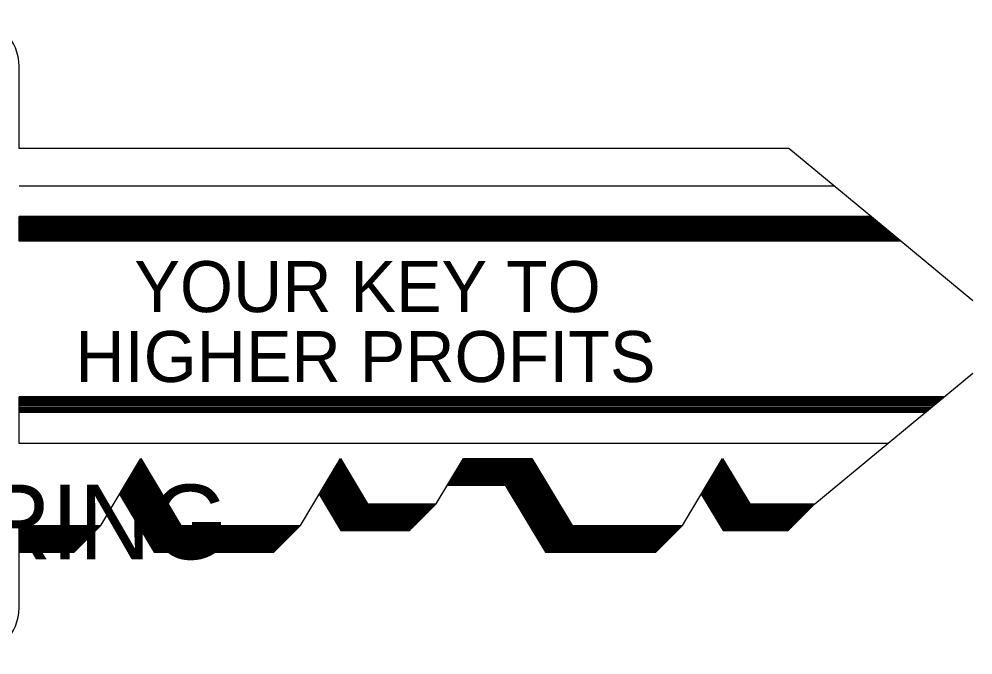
# Model space of a CAD drawing. Extents: x 0 to 13.3, y 0 to 9.3.
# Drawn here: x 1.0443 to 1.466, y 0.4068 to 0.688 of the extents above; entities that cross this region are included whole.
import ezdxf

# ---------------------------------------------------------------- set-up
doc = ezdxf.new("R2010")
doc.units = 0
doc.layers.add('Level 1', color=7, linetype='Continuous')

msp = doc.modelspace()

# ---------------------------------------------------------------- linework, layer by layer
at = {"layer": 'Level 1'}
for p, q in [((1.04429, 0.63074), (1.04429, 0.6672)), ((1.38463, 0.63074), (1.04429, 0.63074)), ((1.434, 0.58991), (1.38471, 0.63074)), ((1.40479, 0.61407), (1.04429, 0.61407)), ((1.04429, 0.58978), (1.04429, 0.60066)), ((1.421, 0.60066), (1.04429, 0.60066)), ((1.42133, 0.60041), (1.04429, 0.60041)), ((1.42163, 0.60016), (1.04429, 0.60016)), ((1.42196, 0.59986), (1.04429, 0.59986)), ((1.42233, 0.59957), (1.04429, 0.59957)), ((1.42267, 0.59928), (1.04429, 0.59928)), ((1.42308, 0.59895), (1.04429, 0.59895)), ((1.42342, 0.59866), (1.04429, 0.59866)), ((1.42383, 0.59832), (1.04429, 0.59832)), ((1.42425, 0.59799), (1.04429, 0.59799)), ((1.42458, 0.5977), (1.04429, 0.5977)), ((1.42496, 0.59736), (1.04429, 0.59736)), ((1.42542, 0.59703), (1.04429, 0.59703)), ((1.42575, 0.59674), (1.04429, 0.59674)), ((1.42608, 0.59645), (1.04429, 0.59645)), ((1.4265, 0.59611), (1.04429, 0.59611)), ((1.42692, 0.59578), (1.04429, 0.59578)), ((1.42729, 0.59545), (1.04429, 0.59545)), ((1.42775, 0.59507), (1.04429, 0.59507)), ((1.42813, 0.59478), (1.04429, 0.59478)), ((1.42488, 0.59745), (1.42475, 0.59757)), ((1.42508, 0.59728), (1.42488, 0.59745)), ((1.42638, 0.5962), (1.42508, 0.59728)), ((1.42696, 0.59574), (1.42638, 0.5962)), ((1.4285, 0.59445), (1.04429, 0.59445)), ((1.42896, 0.59407), (1.04429, 0.59407)), ((1.42938, 0.59374), (1.04429, 0.59374)), ((1.42967, 0.59349), (1.04429, 0.59349)), ((1.43008, 0.59316), (1.04429, 0.59316)), ((1.43046, 0.59282), (1.04429, 0.59282)), ((1.43083, 0.59253), (1.04429, 0.59253)), ((1.43117, 0.59224), (1.04429, 0.59224)), ((1.4315, 0.59199), (1.04429, 0.59199)), ((1.43196, 0.59161), (1.04429, 0.59161)), ((1.43225, 0.59136), (1.04429, 0.59136)), ((1.43258, 0.59107), (1.04429, 0.59107)), ((1.43288, 0.59082), (1.04429, 0.59082)), ((1.43321, 0.59057), (1.04429, 0.59057)), ((1.43346, 0.59036), (1.04429, 0.59036)), ((1.43375, 0.59011), (1.04429, 0.59011)), ((1.43396, 0.58995), (1.04429, 0.58995)), ((1.43417, 0.58978), (1.04429, 0.58978)), ((1.43417, 0.58978), (1.434, 0.58991)), ((1.46604, 0.56345), (1.43417, 0.58978)), ((1.39613, 0.47357), (1.46604, 0.53136)), ((1.45346, 0.52095), (1.04429, 0.52095)), ((1.04429, 0.50028), (1.04429, 0.52095)), ((1.45279, 0.52041), (1.04429, 0.52041)), ((1.45208, 0.51982), (1.04429, 0.51982)), ((1.45129, 0.51916), (1.04429, 0.51916)), ((1.45063, 0.51861), (1.04429, 0.51861)), ((1.44983, 0.51795), (1.04429, 0.51795)), ((1.44913, 0.51736), (1.04429, 0.51736)), ((1.44838, 0.51674), (1.04429, 0.51674)), ((1.44754, 0.51607), (1.04429, 0.51607)), ((1.44679, 0.51545), (1.04429, 0.51545)), ((1.44608, 0.51486), (1.04429, 0.51486)), ((1.44558, 0.51445), (1.04429, 0.51445)), ((1.44513, 0.51407), (1.04429, 0.51407)), ((1.42846, 0.50028), (1.04429, 0.50028)), ((1.08042, 0.46407), (1.09813, 0.49361)), ((1.09813, 0.49361), (1.11579, 0.46407)), ((1.16871, 0.46407), (1.18638, 0.49361)), ((1.18638, 0.49361), (1.19842, 0.47357)), ((1.22875, 0.47357), (1.24075, 0.49361)), ((1.24075, 0.49361), (1.27108, 0.49361)), ((1.27108, 0.49361), (1.28879, 0.46407)), ((1.33763, 0.46407), (1.35533, 0.49361)), ((1.35533, 0.49361), (1.36733, 0.47357)), ((1.09567, 0.48953), (1.10058, 0.48953)), ((1.09588, 0.48986), (1.10038, 0.48986)), ((1.09608, 0.4902), (1.10017, 0.4902)), ((1.09629, 0.49053), (1.09996, 0.49053)), ((1.09646, 0.49086), (1.09975, 0.49086)), ((1.09667, 0.4912), (1.09958, 0.4912)), ((1.09688, 0.49153), (1.09938, 0.49153)), ((1.09708, 0.49186), (1.09917, 0.49186)), ((1.09729, 0.4922), (1.09896, 0.4922)), ((1.09746, 0.49253), (1.09879, 0.49253)), ((1.09767, 0.49286), (1.09858, 0.49286)), ((1.09788, 0.4932), (1.09838, 0.4932)), ((1.18392, 0.48953), (1.18883, 0.48953)), ((1.18413, 0.48986), (1.18863, 0.48986)), ((1.18433, 0.4902), (1.18842, 0.4902)), ((1.18454, 0.49053), (1.18821, 0.49053)), ((1.18471, 0.49086), (1.188, 0.49086)), ((1.18492, 0.4912), (1.18783, 0.4912)), ((1.18513, 0.49153), (1.18763, 0.49153)), ((1.18533, 0.49186), (1.18742, 0.49186)), ((1.18554, 0.4922), (1.18721, 0.4922)), ((1.18571, 0.49253), (1.18704, 0.49253)), ((1.18588, 0.49278), (1.18688, 0.49278)), ((1.18604, 0.49303), (1.18671, 0.49303)), ((1.18617, 0.49328), (1.18658, 0.49328)), ((1.23829, 0.48953), (1.27354, 0.48953)), ((1.2385, 0.48986), (1.27333, 0.48986)), ((1.23871, 0.4902), (1.27313, 0.4902)), ((1.23892, 0.49053), (1.27292, 0.49053)), ((1.23908, 0.49086), (1.27271, 0.49086)), ((1.23929, 0.4912), (1.27254, 0.4912)), ((1.2395, 0.49153), (1.27233, 0.49153)), ((1.23971, 0.49186), (1.27213, 0.49186)), ((1.23992, 0.4922), (1.27192, 0.4922)), ((1.24008, 0.49249), (1.27175, 0.49249)), ((1.24025, 0.49278), (1.27158, 0.49278)), ((1.24042, 0.49307), (1.27142, 0.49307)), ((1.24058, 0.49332), (1.27125, 0.49332)), ((1.35288, 0.48953), (1.35779, 0.48953)), ((1.35308, 0.48986), (1.35758, 0.48986)), ((1.35329, 0.4902), (1.35738, 0.4902)), ((1.3535, 0.49053), (1.35717, 0.49053)), ((1.35367, 0.49086), (1.35696, 0.49086)), ((1.35388, 0.4912), (1.35679, 0.4912)), ((1.35408, 0.49153), (1.35658, 0.49153)), ((1.35429, 0.49186), (1.35638, 0.49186)), ((1.3545, 0.4922), (1.35617, 0.4922)), ((1.35467, 0.49253), (1.356, 0.49253)), ((1.35483, 0.49278), (1.35583, 0.49278)), ((1.09308, 0.4852), (1.10317, 0.4852)), ((1.09329, 0.48553), (1.10296, 0.48553)), ((1.0935, 0.48586), (1.10275, 0.48586)), ((1.09367, 0.4862), (1.10254, 0.4862)), ((1.09388, 0.48653), (1.10238, 0.48653)), ((1.09408, 0.48686), (1.10217, 0.48686)), ((1.09429, 0.4872), (1.10196, 0.4872)), ((1.0945, 0.48753), (1.10175, 0.48753)), ((1.09471, 0.48786), (1.10158, 0.48786)), ((1.09492, 0.4882), (1.10138, 0.4882)), ((1.09513, 0.48853), (1.10117, 0.48853)), ((1.09533, 0.48886), (1.10096, 0.48886)), ((1.09546, 0.4892), (1.10075, 0.4892)), ((1.18133, 0.4852), (1.19142, 0.4852)), ((1.18154, 0.48553), (1.19121, 0.48553)), ((1.18175, 0.48586), (1.191, 0.48586)), ((1.18192, 0.4862), (1.19079, 0.4862)), ((1.18213, 0.48653), (1.19063, 0.48653)), ((1.18233, 0.48686), (1.19042, 0.48686)), ((1.18254, 0.4872), (1.19021, 0.4872)), ((1.18275, 0.48753), (1.19, 0.48753)), ((1.18296, 0.48786), (1.18983, 0.48786)), ((1.18317, 0.4882), (1.18963, 0.4882)), ((1.18338, 0.48853), (1.18942, 0.48853)), ((1.18358, 0.48886), (1.18921, 0.48886)), ((1.18371, 0.4892), (1.189, 0.4892)), ((1.23571, 0.4852), (1.27613, 0.4852)), ((1.23592, 0.48553), (1.27592, 0.48553)), ((1.23613, 0.48586), (1.27571, 0.48586)), ((1.23629, 0.4862), (1.2755, 0.4862)), ((1.2365, 0.48653), (1.27533, 0.48653)), ((1.23671, 0.48686), (1.27513, 0.48686)), ((1.23692, 0.4872), (1.27492, 0.4872)), ((1.23713, 0.48753), (1.27471, 0.48753)), ((1.23729, 0.48786), (1.27454, 0.48786)), ((1.2375, 0.4882), (1.27433, 0.4882)), ((1.23771, 0.48853), (1.27413, 0.48853)), ((1.23792, 0.48886), (1.27392, 0.48886)), ((1.23813, 0.4892), (1.27371, 0.4892)), ((1.35029, 0.4852), (1.36038, 0.4852)), ((1.3505, 0.48553), (1.36017, 0.48553)), ((1.35071, 0.48586), (1.35996, 0.48586)), ((1.35088, 0.4862), (1.35975, 0.4862)), ((1.35108, 0.48653), (1.35958, 0.48653)), ((1.35129, 0.48686), (1.35938, 0.48686)), ((1.3515, 0.4872), (1.35917, 0.4872)), ((1.35171, 0.48753), (1.35896, 0.48753)), ((1.35192, 0.48786), (1.35879, 0.48786)), ((1.35213, 0.4882), (1.35858, 0.4882)), ((1.35233, 0.48853), (1.35838, 0.48853)), ((1.35254, 0.48886), (1.35817, 0.48886)), ((1.35267, 0.4892), (1.35796, 0.4892)), ((1.0905, 0.48086), (1.10575, 0.48086)), ((1.09071, 0.4812), (1.10554, 0.4812)), ((1.09092, 0.48153), (1.10533, 0.48153)), ((1.09113, 0.48186), (1.10517, 0.48186)), ((1.09133, 0.4822), (1.10496, 0.4822)), ((1.09154, 0.48253), (1.10475, 0.48253)), ((1.09175, 0.48286), (1.10454, 0.48286)), ((1.09196, 0.4832), (1.10438, 0.4832)), ((1.09208, 0.48353), (1.10417, 0.48353)), ((1.09229, 0.48386), (1.10396, 0.48386)), ((1.0925, 0.4842), (1.10375, 0.4842)), ((1.09267, 0.48453), (1.10354, 0.48453)), ((1.09288, 0.48486), (1.10338, 0.48486)), ((1.17875, 0.48086), (1.194, 0.48086)), ((1.17896, 0.4812), (1.19379, 0.4812)), ((1.17917, 0.48153), (1.19358, 0.48153)), ((1.17938, 0.48186), (1.19342, 0.48186)), ((1.17958, 0.4822), (1.19321, 0.4822)), ((1.17979, 0.48253), (1.193, 0.48253)), ((1.18, 0.48286), (1.19279, 0.48286)), ((1.18021, 0.4832), (1.19263, 0.4832)), ((1.18033, 0.48353), (1.19242, 0.48353)), ((1.18054, 0.48386), (1.19221, 0.48386)), ((1.18075, 0.4842), (1.192, 0.4842)), ((1.18092, 0.48453), (1.19179, 0.48453)), ((1.18113, 0.48486), (1.19163, 0.48486)), ((1.23371, 0.48186), (1.27813, 0.48186)), ((1.23371, 0.48182), (1.25929, 0.48182)), ((1.23392, 0.4822), (1.27792, 0.4822)), ((1.23413, 0.48253), (1.27771, 0.48253)), ((1.23433, 0.48286), (1.2775, 0.48286)), ((1.2345, 0.4832), (1.27733, 0.4832)), ((1.23471, 0.48353), (1.27713, 0.48353)), ((1.23492, 0.48386), (1.27692, 0.48386)), ((1.23513, 0.4842), (1.27671, 0.4842)), ((1.23529, 0.48453), (1.2765, 0.48453)), ((1.2355, 0.48486), (1.27633, 0.48486)), ((1.25929, 0.48182), (1.277, 0.45228)), ((1.25946, 0.48153), (1.27829, 0.48153)), ((1.25967, 0.4812), (1.2785, 0.4812)), ((1.25988, 0.48086), (1.27871, 0.48086)), ((1.34771, 0.48086), (1.36296, 0.48086)), ((1.34792, 0.4812), (1.36275, 0.4812)), ((1.34813, 0.48153), (1.36254, 0.48153)), ((1.34833, 0.48186), (1.36238, 0.48186)), ((1.34854, 0.4822), (1.36217, 0.4822)), ((1.34875, 0.48253), (1.36196, 0.48253)), ((1.34896, 0.48286), (1.36175, 0.48286)), ((1.34917, 0.4832), (1.36158, 0.4832)), ((1.34929, 0.48353), (1.36138, 0.48353)), ((1.3495, 0.48386), (1.36117, 0.48386)), ((1.34971, 0.4842), (1.36096, 0.4842)), ((1.34988, 0.48453), (1.36075, 0.48453)), ((1.35008, 0.48486), (1.36058, 0.48486)), ((1.08871, 0.47786), (1.104, 0.45228)), ((1.08871, 0.47786), (1.10754, 0.47786)), ((1.08888, 0.4782), (1.10733, 0.4782)), ((1.08892, 0.47753), (1.10775, 0.47753)), ((1.08908, 0.47853), (1.10713, 0.47853)), ((1.08913, 0.4772), (1.10796, 0.4772)), ((1.08929, 0.47886), (1.10696, 0.47886)), ((1.08929, 0.47686), (1.10813, 0.47686)), ((1.0895, 0.4792), (1.10675, 0.4792)), ((1.08967, 0.47953), (1.10654, 0.47953)), ((1.08988, 0.47986), (1.10633, 0.47986)), ((1.09008, 0.4802), (1.10617, 0.4802)), ((1.09029, 0.48053), (1.10596, 0.48053)), ((1.17696, 0.47786), (1.18663, 0.46178)), ((1.17696, 0.47786), (1.19579, 0.47786)), ((1.17713, 0.4782), (1.19558, 0.4782)), ((1.17717, 0.47753), (1.196, 0.47753)), ((1.17733, 0.47853), (1.19538, 0.47853)), ((1.17738, 0.4772), (1.19621, 0.4772)), ((1.17754, 0.47886), (1.19521, 0.47886)), ((1.17754, 0.47686), (1.19638, 0.47686)), ((1.17775, 0.4792), (1.195, 0.4792)), ((1.17792, 0.47953), (1.19479, 0.47953)), ((1.17813, 0.47986), (1.19458, 0.47986)), ((1.17833, 0.4802), (1.19442, 0.4802)), ((1.17854, 0.48053), (1.19421, 0.48053)), ((1.26008, 0.48053), (1.27892, 0.48053)), ((1.26025, 0.4802), (1.27913, 0.4802)), ((1.26046, 0.47986), (1.27929, 0.47986)), ((1.26067, 0.47953), (1.2795, 0.47953)), ((1.26088, 0.4792), (1.27971, 0.4792)), ((1.26108, 0.47886), (1.27992, 0.47886)), ((1.26125, 0.47853), (1.28008, 0.47853)), ((1.26146, 0.4782), (1.28029, 0.4782)), ((1.26167, 0.47786), (1.2805, 0.47786)), ((1.26188, 0.47753), (1.28071, 0.47753)), ((1.26208, 0.4772), (1.28092, 0.4772)), ((1.26225, 0.47686), (1.28108, 0.47686)), ((1.34592, 0.47786), (1.35554, 0.46178)), ((1.34592, 0.47786), (1.36475, 0.47786)), ((1.34608, 0.4782), (1.36454, 0.4782)), ((1.34613, 0.47753), (1.36496, 0.47753)), ((1.34629, 0.47853), (1.36433, 0.47853)), ((1.34633, 0.4772), (1.36517, 0.4772)), ((1.3465, 0.47886), (1.36417, 0.47886)), ((1.3465, 0.47686), (1.36533, 0.47686)), ((1.34671, 0.4792), (1.36396, 0.4792)), ((1.34688, 0.47953), (1.36375, 0.47953)), ((1.34708, 0.47986), (1.36354, 0.47986)), ((1.34729, 0.4802), (1.36338, 0.4802)), ((1.3475, 0.48053), (1.36317, 0.48053)), ((1.0895, 0.47653), (1.10833, 0.47653)), ((1.08971, 0.4762), (1.10846, 0.4762)), ((1.08992, 0.47586), (1.10867, 0.47586)), ((1.09008, 0.47553), (1.10888, 0.47553)), ((1.09029, 0.4752), (1.10908, 0.4752)), ((1.0905, 0.47486), (1.10929, 0.47486)), ((1.09071, 0.47453), (1.1095, 0.47453)), ((1.09092, 0.4742), (1.10971, 0.4742)), ((1.09108, 0.47386), (1.10992, 0.47386)), ((1.09129, 0.47353), (1.11013, 0.47353)), ((1.0915, 0.4732), (1.11033, 0.4732)), ((1.09167, 0.47295), (1.1105, 0.47295)), ((1.09183, 0.47261), (1.11067, 0.47261)), ((1.17775, 0.47653), (1.19658, 0.47653)), ((1.17796, 0.4762), (1.19671, 0.4762)), ((1.17817, 0.47586), (1.19692, 0.47586)), ((1.17833, 0.47553), (1.19713, 0.47553)), ((1.17854, 0.4752), (1.19733, 0.4752)), ((1.17875, 0.47486), (1.19754, 0.47486)), ((1.17896, 0.47453), (1.19775, 0.47453)), ((1.17917, 0.4742), (1.19796, 0.4742)), ((1.17933, 0.47386), (1.19817, 0.47386)), ((1.17954, 0.47353), (1.19838, 0.47353)), ((1.17975, 0.4732), (1.19858, 0.4732)), ((1.17992, 0.47295), (1.19875, 0.47295)), ((1.18008, 0.47261), (1.19892, 0.47261)), ((1.19263, 0.47316), (1.22833, 0.47316)), ((1.19263, 0.47278), (1.22796, 0.47278)), ((1.19263, 0.47241), (1.22758, 0.47241)), ((1.19842, 0.47357), (1.22875, 0.47357)), ((1.21696, 0.46178), (1.22875, 0.47357)), ((1.26246, 0.47653), (1.28129, 0.47653)), ((1.26267, 0.4762), (1.28142, 0.4762)), ((1.26288, 0.47586), (1.28163, 0.47586)), ((1.26304, 0.47553), (1.28183, 0.47553)), ((1.26325, 0.4752), (1.28204, 0.4752)), ((1.26346, 0.47486), (1.28225, 0.47486)), ((1.26367, 0.47453), (1.28246, 0.47453)), ((1.26388, 0.4742), (1.28267, 0.4742)), ((1.26404, 0.47386), (1.28288, 0.47386)), ((1.26425, 0.47353), (1.28308, 0.47353)), ((1.26446, 0.4732), (1.28329, 0.4732)), ((1.26463, 0.47295), (1.28346, 0.47295)), ((1.26479, 0.47261), (1.28363, 0.47261)), ((1.34671, 0.47653), (1.36554, 0.47653)), ((1.34692, 0.4762), (1.36567, 0.4762)), ((1.34713, 0.47586), (1.36588, 0.47586)), ((1.34729, 0.47553), (1.36608, 0.47553)), ((1.3475, 0.4752), (1.36629, 0.4752)), ((1.34771, 0.47486), (1.3665, 0.47486)), ((1.34792, 0.47453), (1.36671, 0.47453)), ((1.34813, 0.4742), (1.36692, 0.4742)), ((1.34829, 0.47386), (1.36713, 0.47386)), ((1.3485, 0.47353), (1.36733, 0.47353)), ((1.34871, 0.4732), (1.36754, 0.4732)), ((1.34888, 0.47295), (1.36771, 0.47295)), ((1.34904, 0.47261), (1.36788, 0.47261)), ((1.36158, 0.47316), (1.39571, 0.47316)), ((1.36158, 0.47278), (1.39533, 0.47278)), ((1.36158, 0.47241), (1.39496, 0.47241)), ((1.36733, 0.47357), (1.39613, 0.47357)), ((1.38433, 0.46178), (1.39613, 0.47357)), ((1.09204, 0.47228), (1.11088, 0.47228)), ((1.09225, 0.47191), (1.11113, 0.47191)), ((1.0925, 0.47149), (1.11138, 0.47149)), ((1.09275, 0.47111), (1.11158, 0.47111)), ((1.093, 0.47066), (1.11188, 0.47066)), ((1.09325, 0.47024), (1.11208, 0.47024)), ((1.09358, 0.46974), (1.11242, 0.46974)), ((1.09383, 0.46928), (1.11267, 0.46928)), ((1.09413, 0.46878), (1.11296, 0.46878)), ((1.09442, 0.46828), (1.11329, 0.46828)), ((1.18029, 0.47228), (1.19913, 0.47228)), ((1.1805, 0.47191), (1.19938, 0.47191)), ((1.18075, 0.47149), (1.19963, 0.47149)), ((1.181, 0.47111), (1.19983, 0.47111)), ((1.18113, 0.47095), (1.22613, 0.47095)), ((1.18142, 0.47045), (1.22563, 0.47045)), ((1.18171, 0.46995), (1.22513, 0.46995)), ((1.182, 0.46949), (1.22467, 0.46949)), ((1.18229, 0.46899), (1.22417, 0.46899)), ((1.18258, 0.46849), (1.22367, 0.46849)), ((1.19263, 0.47195), (1.22713, 0.47195)), ((1.19263, 0.47149), (1.22667, 0.47149)), ((1.265, 0.47228), (1.28383, 0.47228)), ((1.26521, 0.47191), (1.28408, 0.47191)), ((1.26546, 0.47149), (1.28433, 0.47149)), ((1.26571, 0.47111), (1.28454, 0.47111)), ((1.26596, 0.47066), (1.28483, 0.47066)), ((1.26621, 0.47024), (1.28504, 0.47024)), ((1.26654, 0.46974), (1.28538, 0.46974)), ((1.26679, 0.46928), (1.28563, 0.46928)), ((1.26708, 0.46878), (1.28592, 0.46878)), ((1.26738, 0.46828), (1.28625, 0.46828)), ((1.34925, 0.47228), (1.36808, 0.47228)), ((1.34946, 0.47191), (1.36833, 0.47191)), ((1.34971, 0.47149), (1.36858, 0.47149)), ((1.34996, 0.47111), (1.36879, 0.47111)), ((1.35008, 0.47095), (1.3935, 0.47095)), ((1.35038, 0.47045), (1.393, 0.47045)), ((1.35067, 0.46995), (1.3925, 0.46995)), ((1.35096, 0.46949), (1.39204, 0.46949)), ((1.35125, 0.46899), (1.39154, 0.46899)), ((1.35154, 0.46849), (1.39104, 0.46849)), ((1.36158, 0.47195), (1.3945, 0.47195)), ((1.36158, 0.47149), (1.39404, 0.47149)), ((1.04429, 0.42761), (1.04429, 0.46407)), ((1.04429, 0.46407), (1.08042, 0.46407)), ((1.06863, 0.45228), (1.08042, 0.46407)), ((1.09467, 0.46786), (1.11354, 0.46786)), ((1.09492, 0.46745), (1.11379, 0.46745)), ((1.09525, 0.46695), (1.11408, 0.46695)), ((1.0955, 0.46649), (1.11433, 0.46649)), ((1.09579, 0.46599), (1.11463, 0.46599)), ((1.09621, 0.46532), (1.11504, 0.46532)), ((1.09654, 0.46478), (1.11538, 0.46478)), ((1.09688, 0.4642), (1.11571, 0.4642)), ((1.11579, 0.46407), (1.16871, 0.46407)), ((1.15692, 0.45228), (1.16871, 0.46407)), ((1.18288, 0.46799), (1.22317, 0.46799)), ((1.18321, 0.46749), (1.22267, 0.46749)), ((1.18338, 0.46716), (1.22233, 0.46716)), ((1.18363, 0.46678), (1.22196, 0.46678)), ((1.18392, 0.46628), (1.22146, 0.46628)), ((1.18421, 0.46578), (1.22096, 0.46578)), ((1.18446, 0.46536), (1.22054, 0.46536)), ((1.18479, 0.46482), (1.22, 0.46482)), ((1.18508, 0.46432), (1.2195, 0.46432)), ((1.26763, 0.46786), (1.2865, 0.46786)), ((1.26788, 0.46745), (1.28675, 0.46745)), ((1.26821, 0.46695), (1.28704, 0.46695)), ((1.26846, 0.46649), (1.28729, 0.46649)), ((1.26875, 0.46599), (1.28758, 0.46599)), ((1.26917, 0.46532), (1.288, 0.46532)), ((1.2695, 0.46478), (1.28833, 0.46478)), ((1.26983, 0.4642), (1.28867, 0.4642)), ((1.28879, 0.46407), (1.33763, 0.46407)), ((1.32583, 0.45228), (1.33763, 0.46407)), ((1.35183, 0.46799), (1.39054, 0.46799)), ((1.35217, 0.46749), (1.39004, 0.46749)), ((1.35233, 0.46716), (1.38971, 0.46716)), ((1.35258, 0.46678), (1.38933, 0.46678)), ((1.35288, 0.46628), (1.38883, 0.46628)), ((1.35317, 0.46578), (1.38833, 0.46578)), ((1.35342, 0.46536), (1.38792, 0.46536)), ((1.35375, 0.46482), (1.38738, 0.46482)), ((1.35404, 0.46432), (1.38688, 0.46432)), ((1.04429, 0.46366), (1.08, 0.46366)), ((1.04429, 0.46328), (1.07963, 0.46328)), ((1.04429, 0.46291), (1.07925, 0.46291)), ((1.04429, 0.46245), (1.07879, 0.46245)), ((1.04429, 0.46199), (1.07833, 0.46199)), ((1.04429, 0.46145), (1.07779, 0.46145)), ((1.04429, 0.46095), (1.07729, 0.46095)), ((1.04429, 0.46045), (1.07679, 0.46045)), ((1.04429, 0.45999), (1.07633, 0.45999)), ((1.09721, 0.46366), (1.16829, 0.46366)), ((1.09742, 0.46328), (1.16792, 0.46328)), ((1.09767, 0.46291), (1.16754, 0.46291)), ((1.09792, 0.46245), (1.16708, 0.46245)), ((1.09821, 0.46199), (1.16663, 0.46199)), ((1.09854, 0.46145), (1.16608, 0.46145)), ((1.09883, 0.46095), (1.16558, 0.46095)), ((1.09913, 0.46045), (1.16508, 0.46045)), ((1.09938, 0.45999), (1.16463, 0.45999)), ((1.18542, 0.46382), (1.219, 0.46382)), ((1.18567, 0.46336), (1.21854, 0.46336)), ((1.18604, 0.46278), (1.21796, 0.46278)), ((1.18633, 0.46228), (1.21746, 0.46228)), ((1.18663, 0.46178), (1.21696, 0.46178)), ((1.27017, 0.46366), (1.33721, 0.46366)), ((1.27038, 0.46328), (1.33683, 0.46328)), ((1.27063, 0.46291), (1.33646, 0.46291)), ((1.27088, 0.46245), (1.336, 0.46245)), ((1.27117, 0.46199), (1.33554, 0.46199)), ((1.2715, 0.46145), (1.335, 0.46145)), ((1.27179, 0.46095), (1.3345, 0.46095)), ((1.27208, 0.46045), (1.334, 0.46045)), ((1.27233, 0.45999), (1.33354, 0.45999)), ((1.35438, 0.46382), (1.38638, 0.46382)), ((1.35463, 0.46336), (1.38592, 0.46336)), ((1.355, 0.46278), (1.38533, 0.46278)), ((1.35529, 0.46228), (1.38483, 0.46228)), ((1.35554, 0.46178), (1.38433, 0.46178)), ((1.04429, 0.45949), (1.07583, 0.45949)), ((1.04429, 0.45899), (1.07533, 0.45899)), ((1.04429, 0.45849), (1.07483, 0.45849)), ((1.04429, 0.45799), (1.07433, 0.45799)), ((1.04429, 0.45766), (1.074, 0.45766)), ((1.04429, 0.45728), (1.07363, 0.45728)), ((1.04429, 0.45678), (1.07313, 0.45678)), ((1.04429, 0.45628), (1.07263, 0.45628)), ((1.04429, 0.45586), (1.07221, 0.45586)), ((1.09971, 0.45949), (1.16413, 0.45949)), ((1.1, 0.45899), (1.16363, 0.45899)), ((1.10029, 0.45849), (1.16313, 0.45849)), ((1.10058, 0.45799), (1.16263, 0.45799)), ((1.10079, 0.45766), (1.16229, 0.45766)), ((1.101, 0.45728), (1.16192, 0.45728)), ((1.10129, 0.45678), (1.16142, 0.45678)), ((1.10163, 0.45628), (1.16092, 0.45628)), ((1.10188, 0.45586), (1.1605, 0.45586)), ((1.27267, 0.45949), (1.33304, 0.45949)), ((1.27296, 0.45899), (1.33254, 0.45899)), ((1.27325, 0.45849), (1.33204, 0.45849)), ((1.27354, 0.45799), (1.33154, 0.45799)), ((1.27375, 0.45766), (1.33121, 0.45766)), ((1.27396, 0.45728), (1.33083, 0.45728)), ((1.27425, 0.45678), (1.33033, 0.45678)), ((1.27458, 0.45628), (1.32983, 0.45628)), ((1.27483, 0.45586), (1.32942, 0.45586)), ((1.04429, 0.45532), (1.07167, 0.45532)), ((1.04429, 0.45482), (1.07117, 0.45482)), ((1.04429, 0.45432), (1.07067, 0.45432)), ((1.04429, 0.45386), (1.07021, 0.45386)), ((1.04429, 0.45328), (1.06963, 0.45328)), ((1.04429, 0.45278), (1.06913, 0.45278)), ((1.04429, 0.45228), (1.06863, 0.45228)), ((1.10217, 0.45532), (1.15996, 0.45532)), ((1.1025, 0.45482), (1.15946, 0.45482)), ((1.10279, 0.45432), (1.15896, 0.45432)), ((1.10304, 0.45386), (1.1585, 0.45386)), ((1.10342, 0.45328), (1.15792, 0.45328)), ((1.10371, 0.45278), (1.15742, 0.45278)), ((1.104, 0.45228), (1.15692, 0.45228)), ((1.27513, 0.45532), (1.32888, 0.45532)), ((1.27546, 0.45482), (1.32838, 0.45482)), ((1.27575, 0.45432), (1.32788, 0.45432)), ((1.276, 0.45386), (1.32742, 0.45386)), ((1.27638, 0.45328), (1.32683, 0.45328)), ((1.27667, 0.45278), (1.32633, 0.45278)), ((1.277, 0.45228), (1.32583, 0.45228))]:
    msp.add_line(p, q, dxfattribs=at)
for centre, start, end in [((1.02346, 0.6672), 0, 90), ((1.02346, 0.42761), 270, 0)]:
    msp.add_arc(centre, 0.02083, start, end, dxfattribs=at)

# ---------------------------------------------------------------- texts
for s, height, p in [('YOUR KEY TO', 0.0225623, (1.09529, 0.55841)), ('HIGHER PROFITS', 0.0225623, (1.06921, 0.52749)), ('ENGINEERING', 0.0329975, (0.828, 0.44911))]:
    msp.add_text(s, height=height, dxfattribs=at).set_placement(p)

doc.saveas('drawing.dxf')
